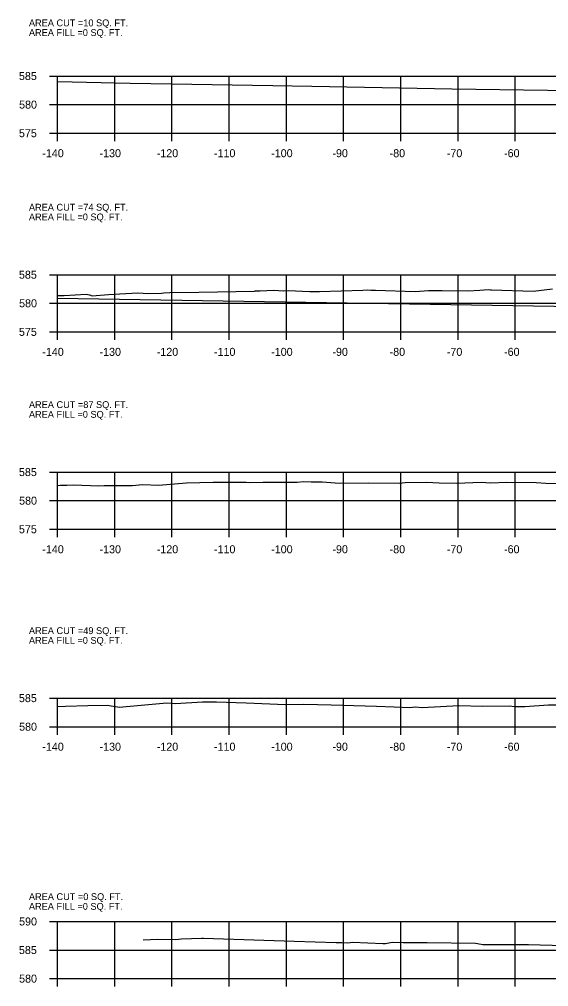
# Model space of a CAD drawing. Extents: x 642114 to 642416, y 286928 to 293347.
# Drawn here: x 642113.6 to 642206.1, y 292947 to 293116.2 of the extents above; entities that cross this region are included whole.
import ezdxf

# ---------------------------------------------------------------- set-up
doc = ezdxf.new("R2010")
doc.units = 0
for name, color, linetype in [('R_Axis', 7, 'Continuous'), ('R_Axis Annot', 7, 'Continuous'), ('R_Draft', 7, 'Continuous'), ('R_Exist Surface', 7, 'Continuous'), ('R_Grid', 7, 'Continuous'), ('R_Water', 7, 'Continuous')]:
    doc.layers.add(name, color=color, linetype=linetype)

msp = doc.modelspace()

# ---------------------------------------------------------------- linework, layer by layer
at = {"layer": 'R_Axis'}
for p, q in [((642118.84, 293106.32), (642120.24, 293106.32)), ((642120.24, 293096.32), (642120.24, 293106.32)), ((642118.84, 293101.32), (642120.24, 293101.32)), ((642118.84, 293096.32), (642120.24, 293096.32)), ((642120.24, 293096.32), (642400.24, 293096.32)), ((642120.24, 293094.92), (642120.24, 293096.32)), ((642130.24, 293094.92), (642130.24, 293096.32)), ((642140.24, 293094.92), (642140.24, 293096.32)), ((642150.24, 293094.92), (642150.24, 293096.32)), ((642160.24, 293094.92), (642160.24, 293096.32)), ((642170.24, 293094.92), (642170.24, 293096.32)), ((642180.24, 293094.92), (642180.24, 293096.32)), ((642190.24, 293094.92), (642190.24, 293096.32)), ((642200.24, 293094.92), (642200.24, 293096.32)), ((642118.84, 293071.57), (642120.24, 293071.57)), ((642120.24, 293061.57), (642120.24, 293071.57)), ((642118.84, 293066.57), (642120.24, 293066.57)), ((642118.84, 293061.57), (642120.24, 293061.57)), ((642120.24, 293061.57), (642400.24, 293061.57)), ((642120.24, 293060.17), (642120.24, 293061.57)), ((642130.24, 293060.17), (642130.24, 293061.57)), ((642140.24, 293060.17), (642140.24, 293061.57)), ((642150.24, 293060.17), (642150.24, 293061.57)), ((642160.24, 293060.17), (642160.24, 293061.57)), ((642170.24, 293060.17), (642170.24, 293061.57)), ((642180.24, 293060.17), (642180.24, 293061.57)), ((642190.24, 293060.17), (642190.24, 293061.57)), ((642200.24, 293060.17), (642200.24, 293061.57)), ((642118.84, 293037.04), (642120.24, 293037.04)), ((642120.24, 293027.04), (642120.24, 293037.04)), ((642118.84, 293032.04), (642120.24, 293032.04)), ((642118.84, 293027.04), (642120.24, 293027.04)), ((642120.24, 293027.04), (642400.24, 293027.04)), ((642120.24, 293025.64), (642120.24, 293027.04)), ((642130.24, 293025.64), (642130.24, 293027.04)), ((642140.24, 293025.64), (642140.24, 293027.04)), ((642150.24, 293025.64), (642150.24, 293027.04)), ((642160.24, 293025.64), (642160.24, 293027.04)), ((642170.24, 293025.64), (642170.24, 293027.04)), ((642180.24, 293025.64), (642180.24, 293027.04)), ((642190.24, 293025.64), (642190.24, 293027.04)), ((642200.24, 293025.64), (642200.24, 293027.04)), ((642118.84, 292997.5), (642120.24, 292997.5)), ((642120.24, 292992.5), (642120.24, 292997.5)), ((642118.84, 292992.5), (642120.24, 292992.5)), ((642120.24, 292992.5), (642400.24, 292992.5)), ((642120.24, 292991.1), (642120.24, 292992.5)), ((642130.24, 292991.1), (642130.24, 292992.5)), ((642140.24, 292991.1), (642140.24, 292992.5)), ((642150.24, 292991.1), (642150.24, 292992.5)), ((642160.24, 292991.1), (642160.24, 292992.5)), ((642170.24, 292991.1), (642170.24, 292992.5)), ((642180.24, 292991.1), (642180.24, 292992.5)), ((642190.24, 292991.1), (642190.24, 292992.5)), ((642200.24, 292991.1), (642200.24, 292992.5)), ((642118.84, 292958.43), (642120.24, 292958.43)), ((642120.24, 292948.43), (642120.24, 292958.43)), ((642118.84, 292953.43), (642120.24, 292953.43)), ((642118.84, 292948.43), (642120.24, 292948.43)), ((642120.24, 292948.43), (642400.24, 292948.43)), ((642120.24, 292947.03), (642120.24, 292948.43)), ((642130.24, 292947.03), (642130.24, 292948.43)), ((642140.24, 292947.03), (642140.24, 292948.43)), ((642150.24, 292947.03), (642150.24, 292948.43)), ((642160.24, 292947.03), (642160.24, 292948.43)), ((642170.24, 292947.03), (642170.24, 292948.43)), ((642180.24, 292947.03), (642180.24, 292948.43)), ((642190.24, 292947.03), (642190.24, 292948.43)), ((642200.24, 292947.03), (642200.24, 292948.43))]:
    msp.add_line(p, q, dxfattribs=at)
at = {"layer": 'R_Exist Surface'}
for points in [[(642120.24, 293105.35), (642132.95, 293105.09), (642140.15, 293104.96), (642157.85, 293104.65), (642164.66, 293104.52), (642183.08, 293104.19), (642189.14, 293104.08), (642205.87, 293103.82), (642210.28, 293103.75), (642227.6, 293103.48), (642231.45, 293103.42), (642235.4, 293103.35), (642253.82, 293103.07), (642257.2, 293103.01), (642276.21, 293102.73), (642277.82, 293102.7), (642288.87, 293102.5), (642290.32, 293102.47), (642301.54, 293102.27)], [(642120.24, 293067.92), (642121.4, 293067.9), (642125.22, 293068.18), (642125.81, 293068.03), (642126.29, 293067.88), (642129.12, 293068.13), (642131.14, 293068.21), (642134.25, 293068.41), (642136.16, 293068.26), (642138.38, 293068.36), (642138.79, 293068.38), (642139.86, 293068.48), (642144.93, 293068.54), (642154.69, 293068.71), (642154.77, 293068.72), (642155.65, 293068.74), (642157.99, 293068.86), (642159.71, 293068.77), (642160.55, 293068.8), (642164.32, 293068.62), (642166.05, 293068.62), (642173.62, 293068.88), (642174.41, 293068.92), (642174.97, 293068.87), (642175.82, 293068.88), (642182.72, 293068.63), (642185.05, 293068.81), (642187.44, 293068.79), (642192, 293068.72), (642194.04, 293068.84), (642195.56, 293068.96), (642195.92, 293068.94), (642196.09, 293068.93), (642203.39, 293068.66), (642206.75, 293069.08)], [(642120.24, 293034.69), (642120.7, 293034.75), (642121.48, 293034.74), (642121.86, 293034.77), (642123.05, 293034.8), (642127.48, 293034.66), (642128.39, 293034.67), (642133.26, 293034.71), (642135.15, 293034.88), (642137.89, 293034.75), (642142.79, 293035.18), (642147.46, 293035.26), (642153.19, 293035.25), (642153.74, 293035.24), (642156.1, 293035.28), (642162.14, 293035.29), (642163.25, 293035.37), (642164.54, 293035.31), (642166.48, 293035.33), (642169.49, 293035.09), (642174.62, 293035.15), (642179.92, 293035.09), (642180.99, 293035.19), (642184.72, 293035.25), (642186.91, 293035.15), (642189.98, 293035.1), (642194.26, 293035.25), (642195.9, 293035.18), (642198.74, 293035.3), (642203.87, 293035.19), (642205.6, 293035.08), (642209.69, 293035)], [(642120.24, 292996.05), (642121.63, 292996.09), (642125.54, 292996.2), (642128.9, 292996.24), (642131.07, 292995.93), (642132.22, 292996.01), (642132.91, 292996.08), (642139.35, 292996.66), (642140.88, 292996.54), (642145.6, 292996.84), (642148, 292996.86), (642153.2, 292996.7), (642160.06, 292996.39), (642163.31, 292996.47), (642168.06, 292996.31), (642175.98, 292996.12), (642179.06, 292996), (642181.81, 292995.83), (642182.76, 292995.95), (642183.96, 292995.88), (642190.37, 292996.2), (642194.49, 292996.12), (642199.19, 292996.17), (642200.18, 292996.04), (642201.91, 292996.04), (642206.05, 292996.32), (642209, 292996.35)], [(642135.23, 292955.24), (642137.79, 292955.32), (642140.83, 292955.29), (642141.9, 292955.39), (642145.4, 292955.53), (642145.56, 292955.53), (642145.74, 292955.52), (642161.58, 292954.97), (642168.91, 292954.76), (642169.95, 292954.74), (642170.9, 292954.7), (642171.84, 292954.78), (642177.1, 292954.57), (642177.56, 292954.57), (642178.75, 292954.81), (642180.66, 292954.75), (642184.82, 292954.75), (642193.26, 292954.62), (642194.26, 292954.45), (642194.59, 292954.4), (642202.58, 292954.42), (642208.72, 292954.25)]]:
    msp.add_lwpolyline(points, dxfattribs=at)
at = {"layer": 'R_Grid'}
for p, q in [((642120.24, 293106.32), (642400.24, 293106.32)), ((642120.24, 293096.32), (642120.24, 293106.32)), ((642130.24, 293096.32), (642130.24, 293106.32)), ((642140.24, 293096.32), (642140.24, 293106.32)), ((642150.24, 293096.32), (642150.24, 293106.32)), ((642160.24, 293096.32), (642160.24, 293106.32)), ((642170.24, 293096.32), (642170.24, 293106.32)), ((642180.24, 293096.32), (642180.24, 293106.32)), ((642190.24, 293096.32), (642190.24, 293106.32)), ((642200.24, 293096.32), (642200.24, 293106.32)), ((642120.24, 293101.32), (642400.24, 293101.32)), ((642120.24, 293096.32), (642400.24, 293096.32)), ((642120.24, 293071.57), (642400.24, 293071.57)), ((642120.24, 293061.57), (642120.24, 293071.57)), ((642130.24, 293061.57), (642130.24, 293071.57)), ((642140.24, 293061.57), (642140.24, 293071.57)), ((642150.24, 293061.57), (642150.24, 293071.57)), ((642160.24, 293061.57), (642160.24, 293071.57)), ((642170.24, 293061.57), (642170.24, 293071.57)), ((642180.24, 293061.57), (642180.24, 293071.57)), ((642190.24, 293061.57), (642190.24, 293071.57)), ((642200.24, 293061.57), (642200.24, 293071.57)), ((642120.24, 293066.57), (642400.24, 293066.57)), ((642120.24, 293061.57), (642400.24, 293061.57)), ((642120.24, 293037.04), (642400.24, 293037.04)), ((642120.24, 293027.04), (642120.24, 293037.04)), ((642130.24, 293027.04), (642130.24, 293037.04)), ((642140.24, 293027.04), (642140.24, 293037.04)), ((642150.24, 293027.04), (642150.24, 293037.04)), ((642160.24, 293027.04), (642160.24, 293037.04)), ((642170.24, 293027.04), (642170.24, 293037.04)), ((642180.24, 293027.04), (642180.24, 293037.04)), ((642190.24, 293027.04), (642190.24, 293037.04)), ((642200.24, 293027.04), (642200.24, 293037.04)), ((642120.24, 293032.04), (642400.24, 293032.04)), ((642120.24, 293027.04), (642400.24, 293027.04)), ((642120.24, 292997.5), (642400.24, 292997.5)), ((642120.24, 292992.5), (642120.24, 292997.5)), ((642130.24, 292992.5), (642130.24, 292997.5)), ((642140.24, 292992.5), (642140.24, 292997.5)), ((642150.24, 292992.5), (642150.24, 292997.5)), ((642160.24, 292992.5), (642160.24, 292997.5)), ((642170.24, 292992.5), (642170.24, 292997.5)), ((642180.24, 292992.5), (642180.24, 292997.5)), ((642190.24, 292992.5), (642190.24, 292997.5)), ((642200.24, 292992.5), (642200.24, 292997.5)), ((642120.24, 292992.5), (642400.24, 292992.5)), ((642120.24, 292958.43), (642400.24, 292958.43)), ((642120.24, 292948.43), (642120.24, 292958.43)), ((642130.24, 292948.43), (642130.24, 292958.43)), ((642140.24, 292948.43), (642140.24, 292958.43)), ((642150.24, 292948.43), (642150.24, 292958.43)), ((642160.24, 292948.43), (642160.24, 292958.43)), ((642170.24, 292948.43), (642170.24, 292958.43)), ((642180.24, 292948.43), (642180.24, 292958.43)), ((642190.24, 292948.43), (642190.24, 292958.43)), ((642200.24, 292948.43), (642200.24, 292958.43)), ((642120.24, 292953.43), (642400.24, 292953.43)), ((642120.24, 292948.43), (642400.24, 292948.43))]:
    msp.add_line(p, q, dxfattribs=at)
at = {"layer": 'R_Water'}
msp.add_lwpolyline([(642120.24, 293067.48), (642239.59, 293065.55)], dxfattribs=at)

# ---------------------------------------------------------------- texts
at = {"layer": 'R_Axis Annot'}
for s, p in [('585', (642113.49, 293105.62)), ('580', (642113.52, 293100.62)), ('575', (642113.49, 293095.62)), ('-140', (642117.58, 293092.12)), ('-130', (642127.58, 293092.12)), ('-120', (642137.58, 293092.12)), ('-110', (642147.58, 293092.12)), ('-100', (642157.58, 293092.12)), ('-90', (642168.28, 293092.12)), ('-80', (642178.28, 293092.12)), ('-70', (642188.28, 293092.12)), ('-60', (642198.28, 293092.12)), ('585', (642113.49, 293070.87)), ('580', (642113.52, 293065.87)), ('575', (642113.49, 293060.87)), ('-140', (642117.58, 293057.37)), ('-130', (642127.58, 293057.37)), ('-120', (642137.58, 293057.37)), ('-110', (642147.58, 293057.37)), ('-100', (642157.58, 293057.37)), ('-90', (642168.28, 293057.37)), ('-80', (642178.28, 293057.37)), ('-70', (642188.28, 293057.37)), ('-60', (642198.28, 293057.37)), ('585', (642113.49, 293036.34)), ('580', (642113.52, 293031.34)), ('575', (642113.49, 293026.34)), ('-140', (642117.58, 293022.84)), ('-130', (642127.58, 293022.84)), ('-120', (642137.58, 293022.84)), ('-110', (642147.58, 293022.84)), ('-100', (642157.58, 293022.84)), ('-90', (642168.28, 293022.84)), ('-80', (642178.28, 293022.84)), ('-70', (642188.28, 293022.84)), ('-60', (642198.28, 293022.84)), ('585', (642113.49, 292996.8)), ('580', (642113.52, 292991.8)), ('-140', (642117.58, 292988.3)), ('-130', (642127.58, 292988.3)), ('-120', (642137.58, 292988.3)), ('-110', (642147.58, 292988.3)), ('-100', (642157.58, 292988.3)), ('-90', (642168.28, 292988.3)), ('-80', (642178.28, 292988.3)), ('-70', (642188.28, 292988.3)), ('-60', (642198.28, 292988.3)), ('590', (642113.52, 292957.73)), ('585', (642113.49, 292952.73)), ('580', (642113.52, 292947.73))]:
    msp.add_text(s, height=1.4, dxfattribs=at).set_placement(p)
at = {"layer": 'R_Draft'}
for s, p in [('AREA CUT =10 SQ. FT.', (642115.24, 293115.02)), ('AREA FILL =0 SQ. FT.', (642115.24, 293113.32)), ('AREA CUT =74 SQ. FT.', (642115.24, 293082.77)), ('AREA FILL =0 SQ. FT.', (642115.24, 293081.07)), ('AREA CUT =87 SQ. FT.', (642115.24, 293048.24)), ('AREA FILL =0 SQ. FT.', (642115.24, 293046.54)), ('AREA CUT =49 SQ. FT.', (642115.24, 293008.7)), ('AREA FILL =0 SQ. FT.', (642115.24, 293007)), ('AREA CUT =0 SQ. FT.', (642115.24, 292962.17)), ('AREA FILL =0 SQ. FT.', (642115.24, 292960.47))]:
    msp.add_text(s, height=1.2, dxfattribs=at).set_placement(p)

doc.saveas('drawing.dxf')
